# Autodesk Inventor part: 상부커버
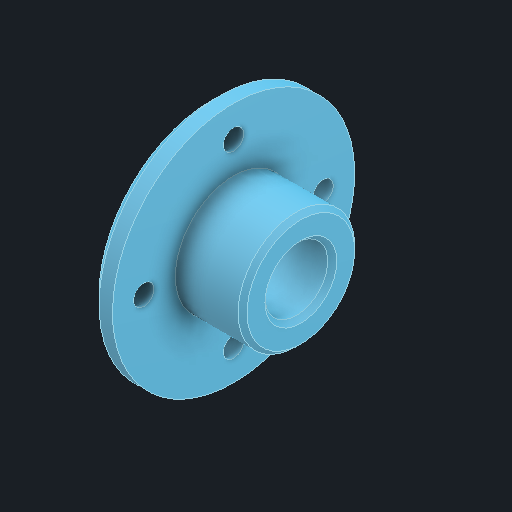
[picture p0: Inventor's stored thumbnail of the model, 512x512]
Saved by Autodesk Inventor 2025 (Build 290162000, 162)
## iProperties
Created: 2025-08
Part Number: 상부커버
Material: 알루미늄 6061
Document SubType Name: Modeling
Designer: infra11
Density: 2.71 g/cm^3
Appearance: 기본값
Author: jhkim
Sending System: Autodesk Inventor 2026
Preprocessor: ST-DEVELOPER v20.1
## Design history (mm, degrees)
feature "솔리드1"
node "솔리드2"
